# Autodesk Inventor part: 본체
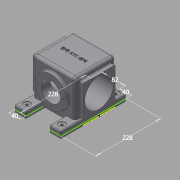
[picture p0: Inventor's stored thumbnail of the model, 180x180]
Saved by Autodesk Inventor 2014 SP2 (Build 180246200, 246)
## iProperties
Created: 2026-01
Part Number: 본체
Material: Generic
Document SubType Name: Modeling
Designer: Administrator
Density: 1 g/cm^3
Appearance: Default
Author: Administrator
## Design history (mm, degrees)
sketch "스케치1"
  geometry: L1 (-74, -71)-(74, -71); L2 (74, -71)-(74, 71); L3 (74, 71)-(-74, 71); L4 (-74, 71)-(-74, -71); L5 (-74, -71)-(74, 71); L6 (74, -71)-(-74, 71); 1 further point
  constraints: 12 end point, 2 midpoint, 2 parallel, 1 horizontal, 1 perpendicular
  dimensions: "d0" = 148 distance of L2.end L3.end; "d1" = 142 distance of L3.end L1.start
extrude "돌출1" new body sketch "스케치1" distance "d2" = 142; taper "d3" = 0 deg
sketch "스케치2"
  geometry: L1 (0, 142)-(-142, 142) reference; L2 (0, 142)-(-142, 142); L3 (-127, 15)-(-15, 15); L4 (-15, 15)-(-15, 127); L5 (-15, 127)-(-127, 127); L6 (-127, 127)-(-127, 15); L7 (-127, 15)-(-71, 71); L8 (-15, 15)-(-71, 71); 1 further point
  constraints: 16 end point, 3 equal length, 1 horizontal, 1 perpendicular
  dimensions: "d5" = 112 distance of L5.end L4.end; "d6" = 112 distance of L4.end L3.end
extrude "돌출2" join sketch "스케치2" distance "d7" = 13; taper "d8" = 0 deg
sketch "스케치4"
  geometry: C1 r 50 at (-71, 71); 1 further point
  constraints: 1 centre point
  dimensions: "d11" = 100 diameter of C1
extrude "돌출3" cut sketch "스케치4" distance "d12" = 200; taper "d13" = 0 deg
sketch "스케치5"
  geometry: L1 (-112, 30)-(-30, 30); L2 (-30, 30)-(-30, 112); L3 (-30, 112)-(-112, 112); L4 (-112, 112)-(-112, 30); L5 (-112, 30)-(-30, 112); L6 (-30, 30)-(-112, 112); C1 r 50 at (-71, 71) reference; C2 r 15 at (-30, 112); C3 r 15 at (-112, 112); C4 r 15 at (-112, 30); C5 r 15 at (-30, 30); 1 further point
  constraints: 12 end point, 4 centre point, 4 coincident, 2 midpoint, 2 parallel, 1 horizontal, 1 perpendicular
  dimensions: "d14" = 82 distance of L3.end L2.end; "d15" = 82 distance of L2.end L1.end; "d16" = 30 diameter of C2; "d17" = 30 diameter of C3; "d18" = 30 diameter of C4; "d19" = 30 diameter of C5
hole "구멍1" sketch "스케치5" at (-30, 30) diameter "d20" = 4.917; stored, may be unused: countersink angle "d24" = 82 deg, drill point angle "d26" = 118 deg; dims "d21" = 12, "d22" = 3.023, "d23" = 2, "d25" = 14
fillet "모깎기4" dims "d33" = 10
sketch "스케치6"
  geometry: L1 (-74, -71)-(-74, 61) reference; L2 (74, 61)-(-74, 61) reference; L3 (74, 61)-(74, -71) reference; L4 (74, -71)-(-74, -71) reference; C1 r 54 at (0, 0); C2 r 34 at (0, 0); 1 further point
  constraints: 2 centre point, 2 coincident
  dimensions: "d34" = 108 diameter of C1; "d35" = 68 diameter of C2
  node "절단 모서리 투영2"
extrude "돌출4" join sketch "스케치6" distance "d36" = 11; taper "d37" = 0 deg
sketch "스케치7"
  geometry: C1 r 34 at (0, 0) reference
extrude "돌출5" cut sketch "스케치7" distance "d38" = 50; taper "d39" = 0 deg
fillet "모깎기5" dims "d40" = 10
fillet "모깎기6" dims "d41" = 3
sketch "스케치8"
  geometry: C1 r 54 at (0, 0) reference; 5 further points
  constraints: 1 coincident
  dimensions: "d49" = 44 distance of C1.centre point (44, 0)
hole "구멍2" sketch "스케치8" at (-44, 0) diameter "d42" = 4.917; stored, may be unused: countersink angle "d46" = 82 deg, drill point angle "d48" = 118 deg; dims "d43" = 12, "d44" = 3.023, "d45" = 2, "d47" = 14
sketch "스케치9"
  geometry: L1 (0, -54)-(0, -34); L2 (0, 34)-(0, 54); C1 r 10 at (44.487, 0); C2 r 10 at (0, 44); C3 r 10 at (0, -44); A1 r 34 centre (0, 0) between (0, -34) and (0, 34) reference; A2 r 54 centre (0, 0) between (0, -54) and (0, 54) reference
  constraints: 4 end point, 4 point on circle, 3 centre point, 2 midpoint, 1 collinear, 1 vertical
  dimensions: "d50" = 20 distance of L1.start L1.end; "d51" = 20 diameter of C1; "d52" = 20 diameter of C2; "d53" = 20 diameter of C3
hole "구멍3" sketch "스케치9" at (0, 0), (0, 44), (44.487, 0), (0, -44) diameter "d54" = 4.917; stored, may be unused: countersink angle "d58" = 82 deg, drill point angle "d60" = 118 deg; dims "d55" = 12, "d56" = 3.023, "d57" = 2, "d59" = 14
sketch "스케치10"
  geometry: L1 (138, 10)-(138, 132) reference; L2 (105, 198.771)-(105, -29.229); L3 (105, -29.229)-(145, -29.229); L4 (105, 198.771)-(145, 198.771); L5 (145, 198.771)-(145, -29.229); L6 (151, 127)-(151, 15) reference; L7 (23, 198.771)-(23, -29.229); L8 (23, 198.771)-(-17, 198.771); L9 (-17, -29.229)-(-17, 198.771); L10 (23, -29.229)-(-17, -29.229); 2 further points
  constraints: 16 end point, 4 perpendicular, 3 parallel, 1 midpoint, 1 vertical
  dimensions: "d64" = 40 distance of L2.end L3.end; "d65" = 228 distance of L4.end L3.end; "d66" = 228 distance of L7.start L7.end; "d67" = 40 distance of L7.start L8.end; "d68" = 82 distance between parallel lines of L2 L7
extrude "돌출6" join sketch "스케치10" distance "d71" = 14; taper "d72" = 0 deg
fillet "모깎기7" dims "d73" = 3
fillet "모깎기8" dims "d74" = 3
sketch "스케치11"
  geometry: L1 (-10, -132)-(-10, -10) reference; L2 (0, 0)-(20, 0) reference; L3 (20, 0)-(108, 0) reference; L4 (108, 26.229)-(108, 0) reference; L5 (142, 26.229)-(108, 26.229) reference; L6 (142, -195.771)-(142, 26.229) reference; L7 (108, -195.771)-(142, -195.771) reference; L8 (108, -142)-(108, -195.771) reference; L9 (128, -142)-(108, -142) reference; L10 (138, -10)-(138, -132) reference; L11 (108, 0)-(128, 0) reference; L12 (20, -142)-(0, -142) reference; L13 (20, -195.771)-(20, -142) reference; L14 (-14, -195.771)-(20, -195.771) reference; L15 (-14, 26.229)-(-14, -195.771) reference; L16 (20, 26.229)-(-14, 26.229) reference; L17 (20, 0)-(20, 26.229) reference; L18 (108, -142)-(64, -142) reference; L19 (64, -142)-(20, -142) reference; C1 r 12 at (125, 13.114); C2 r 12 at (3, 13.114); C3 r 12 at (125, -174.886); C4 r 12 at (3, -174.886); A1 r 10 centre (0, -132) between (-10, -132) and (0, -142) reference; A2 r 10 centre (0, -10) between (0, 0) and (-10, -10) reference; A3 r 10 centre (128, -132) between (128, -142) and (138, -132) reference; A4 r 10 centre (128, -10) between (138, -10) and (128, 0) reference; 1 further point
  constraints: 4 centre point, 1 horizontal alignment
  dimensions: "d75" = 24 diameter of C1; "d76" = 24 diameter of C2; "d79" = 24 diameter of C3; "d80" = 24 diameter of C4; "d81" = 122 distance of C1.centre C2.centre; "d82" = 188 distance of C3.centre C1.centre; "d83" = 188 distance of C2.centre C4.centre; "d84" = 122 distance of C3.centre C4.centre
extrude "돌출7" cut sketch "스케치11" distance "d85" = 2; taper "d86" = 0 deg
sketch "스케치12"
  geometry: C1 r 12 at (3, 13.114) reference; C2 r 12 at (3, -174.886) reference; C3 r 4.5 at (3, -174.886); C4 r 4.5 at (3, 13.114); 1 further point
  constraints: 2 centre point, 2 coincident
  dimensions: "d87" = 9 diameter of C3; "d88" = 9 diameter of C4
extrude "돌출8" cut sketch "스케치12" distance "d89" = 14; taper "d90" = 0 deg
sketch "스케치13"
  geometry: C1 r 12 at (125, 13.114) reference; C2 r 12 at (125, -174.886) reference; C3 r 4.5 at (125, 13.114); C4 r 4.5 at (125, -174.886); 1 further point
  constraints: 2 centre point, 2 coincident
  dimensions: "d91" = 9 diameter of C3; "d92" = 9 diameter of C4
extrude "돌출9" cut sketch "스케치13" distance "d93" = 14; taper "d94" = 0 deg
sketch "스케치15"
  geometry: L1 (18.392, -55.08)-(110.631, -55.08); L2 (110.631, -55.08)-(110.631, -67.089); L3 (110.631, -67.089)-(18.392, -67.089); L4 (18.392, -67.089)-(18.392, -55.08); L5 (128, 0)-(128, -122) reference; L6 (0, 0)-(128, 0) reference; L7 (0, -122)-(0, 0) reference; L8 (128, -122)-(0, -122) reference; L9 (0, -61)-(128, -61); L10 (64, -122)-(64, 0); 1 further point
  constraints: 4 end point, 4 midpoint, 2 other
feature "엠보싱1" sketch "스케치15" dims "d0" = 148, "d1" = 142, "d95" = 0.5, "d96" = 0
fillet "모깎기9" dims "d97" = 3
fillet "모깎기10" dims "d98" = 3
fillet "모깎기11" dims "d99" = 3
sketch "스케치16"
  geometry: L1 (-3, -32.229)-(-37, -32.229) reference; L2 (0, 0)-(0, -29.229) reference; L3 (82, 0)-(0, 0) reference; L4 (82, 0)-(82, -29.229) reference; L5 (85, -32.229)-(119, -32.229) reference; L6 (122, -29.229)-(122, 192.771) reference; L7 (119, 195.771)-(85, 195.771) reference; L8 (82, 136)-(82, 192.771) reference; L9 (0, 136)-(82, 136) reference; L10 (0, 192.771)-(0, 136) reference; L11 (-37, 195.771)-(-3, 195.771) reference; L12 (-40, -29.229)-(-40, 192.771) reference; L13 (0, 136)-(82, 136); L14 (82, 0)-(0, 0); L15 (0, 136)-(0, 0); L16 (82, 136)-(82, 0); C1 r 4.5 at (102, -16.114) reference; C2 r 4.5 at (102, 171.886) reference; C3 r 4.5 at (-20, -16.114) reference; C4 r 4.5 at (-20, 171.886) reference; A1 r 3 centre (-37, -29.229) between (-40, -29.229) and (-37, -32.229) reference; A2 r 3 centre (-3, -29.229) between (-3, -32.229) and (0, -29.229) reference; A3 r 3 centre (85, -29.229) between (82, -29.229) and (85, -32.229) reference; A4 r 3 centre (119, -29.229) between (119, -32.229) and (122, -29.229) reference; A5 r 3 centre (119, 192.771) between (122, 192.771) and (119, 195.771) reference; A6 r 3 centre (85, 192.771) between (85, 195.771) and (82, 192.771) reference; A7 r 3 centre (-3, 192.771) between (0, 192.771) and (-3, 195.771) reference; A8 r 3 centre (-37, 192.771) between (-37, 195.771) and (-40, 192.771) reference; 1 further point
  constraints: 8 end point, 2 collinear, 2 perpendicular
extrude "돌출10" join sketch "스케치16" distance "d100" = 8; taper "d101" = 0 deg
node "솔리드1"
pattern_circular "원형 패턴1" dims angle "d31" = 360 deg
mirror "대칭1"
mirror "대칭2"
node "절단 모서리 투영3"
other parameters: "d4" = 71
